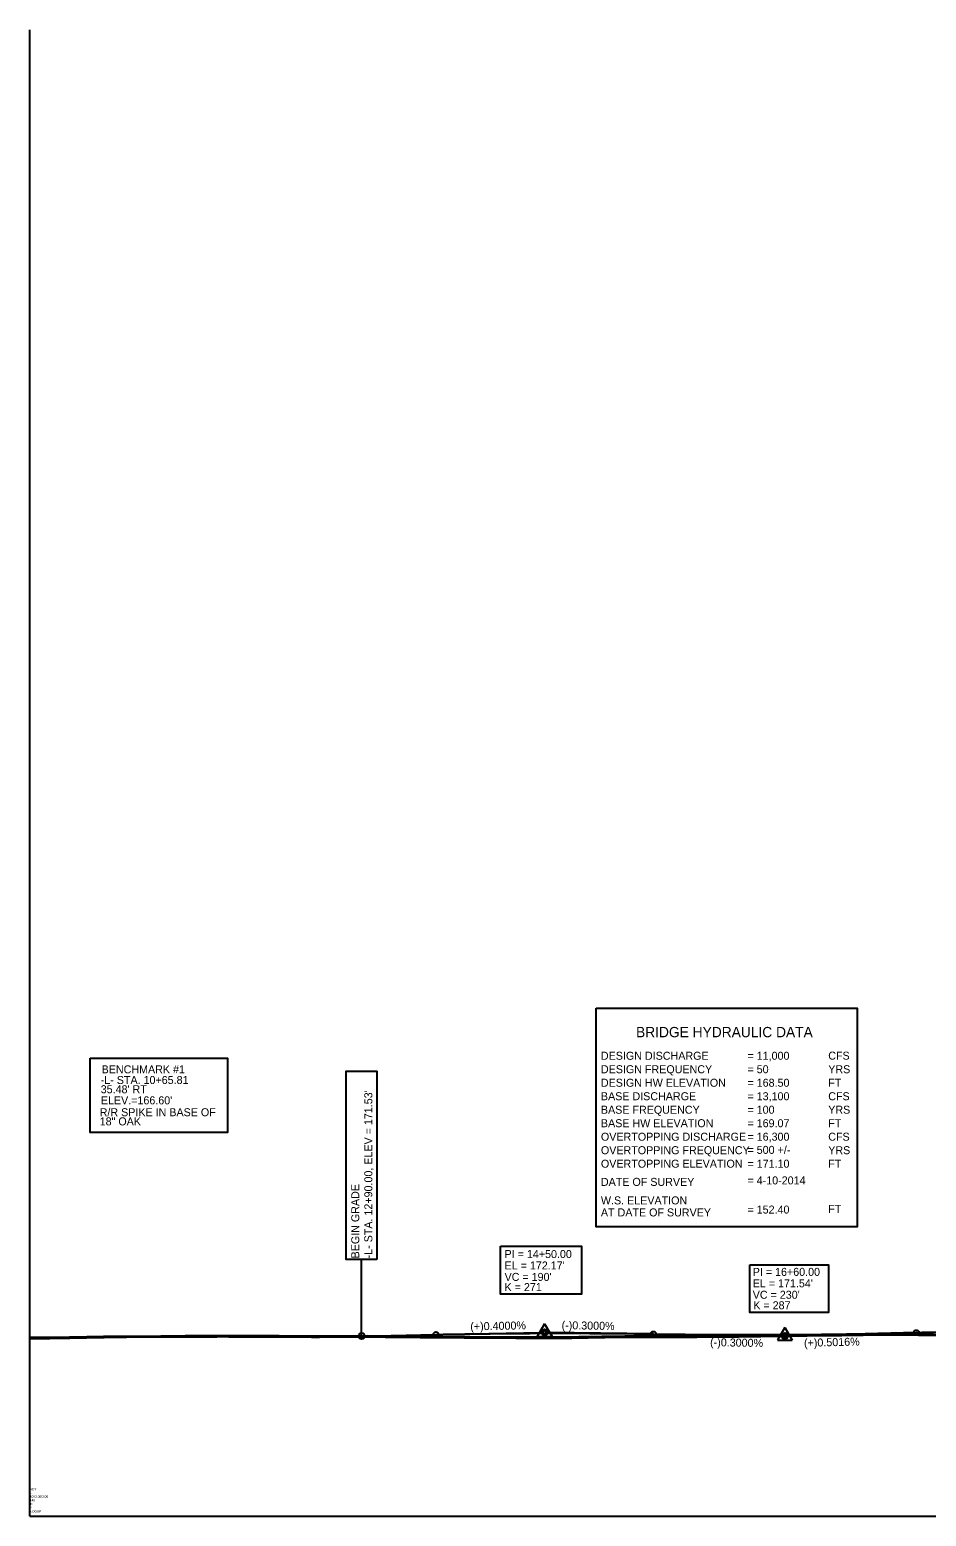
# Model space of a CAD drawing. Extents: x 2321227 to 2323611, y 920570 to 921870.
# Drawn here: x 2321227 to 2322011, y 920570 to 921870 of the extents above; entities that cross this region are included whole.
import ezdxf

# ---------------------------------------------------------------- set-up
doc = ezdxf.new("R2010")
doc.units = 0
for name, color, linetype in [('Exist Profile Cell', 7, 'Continuous'), ('Exist Vertical Profile Ground Line', 7, 'Continuous'), ('Prop Grid Mask', 7, 'Continuous'), ('Prop PFL Text', 7, 'Continuous'), ('Prop PFL VPI Symbol CELL', 7, 'Continuous'), ('Prop Vertical Profile Curve Label', 7, 'Continuous'), ('Prop Vertical Profile Grade', 7, 'Continuous'), ('Prop Vertical Profile Grade Label', 7, 'Continuous'), ('Prop VPI Label', 7, 'Continuous'), ('Scratch_Level_1', 7, 'Continuous'), ('Scratch_Level_2', 7, 'Continuous'), ('Scratch_Level_5', 7, 'Continuous')]:
    doc.layers.add(name, color=color, linetype=linetype)

# ---------------------------------------------------------------- blocks, each defined once
blk = doc.blocks.new('Profile VPI Symbol')
at = {"layer": 'Prop PFL VPI Symbol CELL'}
for p, q in [((-0.001, 0.147), (-0.13, -0.077)), ((-0.001, 0.147), (0.129, -0.077)), ((-0.13, -0.077), (0.129, -0.077))]:
    blk.add_line(p, q, dxfattribs=at)
for radius in [0.035, 0.024]:
    blk.add_circle((-0.001, -0.003), radius, dxfattribs=at)

msp = doc.modelspace()

# ---------------------------------------------------------------- linework, layer by layer
at = {"layer": 'Exist Profile Cell'}
for q in [(2321227, 921870.1), (2323610.7, 920570.1), (2321227, 920570.1)]:
    msp.add_line((2321227, 920570.1), q, dxfattribs=at)
at = {"layer": 'Exist Vertical Profile Ground Line'}
for p, q in [((2321227, 920725.5), (2321244.4, 920725.5)), ((2321244.4, 920725.5), (2321261.6, 920725.9)), ((2321261.6, 920725.9), (2321262, 920725.9)), ((2321262, 920725.9), (2321291.3, 920726.5)), ((2321291.3, 920726.5), (2321292, 920726.5)), ((2321292, 920726.5), (2321311.2, 920726.6)), ((2321311.2, 920726.6), (2321311.5, 920726.6)), ((2321311.5, 920726.6), (2321341.6, 920726.9)), ((2321341.6, 920726.9), (2321342.1, 920726.9)), ((2321342.1, 920726.9), (2321347.1, 920726.9)), ((2321347.1, 920726.9), (2321349, 920726.9)), ((2321349, 920726.9), (2321355.9, 920726.9)), ((2321355.9, 920726.9), (2321362.8, 920727)), ((2321362.8, 920727), (2321366.5, 920727)), ((2321366.5, 920727), (2321369.7, 920727)), ((2321369.7, 920727), (2321376.6, 920727.1)), ((2321376.6, 920727.1), (2321383.5, 920727.1)), ((2321383.5, 920727.1), (2321390.4, 920727.1)), ((2321390.4, 920727.1), (2321395.8, 920727.2)), ((2321395.8, 920727.2), (2321396.2, 920727.2)), ((2321396.2, 920727.2), (2321397.3, 920727.2)), ((2321397.3, 920727.2), (2321400.9, 920727.1)), ((2321400.9, 920727.1), (2321401.6, 920727.1)), ((2321401.6, 920727.1), (2321404.3, 920727.1)), ((2321404.3, 920727.1), (2321411.2, 920727.1)), ((2321411.2, 920727.1), (2321418.1, 920727.1)), ((2321418.1, 920727.1), (2321425, 920727)), ((2321425, 920727), (2321430.6, 920727)), ((2321430.6, 920727), (2321431.2, 920727)), ((2321431.2, 920727), (2321431.9, 920727)), ((2321431.9, 920727), (2321438.8, 920727)), ((2321438.8, 920727), (2321445, 920727)), ((2321445, 920727), (2321445.7, 920726.9)), ((2321445.7, 920726.9), (2321446.6, 920726.9)), ((2321446.6, 920726.9), (2321452.6, 920726.9)), ((2321452.6, 920726.9), (2321459.5, 920726.9)), ((2321459.5, 920726.9), (2321466.4, 920726.9)), ((2321466.4, 920726.9), (2321473.3, 920726.8)), ((2321473.3, 920726.8), (2321475.5, 920726.8)), ((2321475.5, 920726.8), (2321480.2, 920726.8)), ((2321480.2, 920726.8), (2321491.7, 920726.9)), ((2321491.7, 920726.9), (2321493.4, 920726.9)), ((2321493.4, 920726.9), (2321522.3, 920727)), ((2321522.3, 920727), (2321537.7, 920726.8)), ((2321537.7, 920726.8), (2321538.2, 920726.8)), ((2321538.2, 920726.8), (2321568.2, 920726.5)), ((2321568.2, 920726.5), (2321581.5, 920726.3)), ((2321581.5, 920726.3), (2321606.7, 920726.1)), ((2321606.7, 920726.1), (2321611.5, 920726.1)), ((2321611.5, 920726.1), (2321614.5, 920726)), ((2321614.5, 920726), (2321627.5, 920726)), ((2321627.5, 920726), (2321651.9, 920725.8)), ((2321651.9, 920725.8), (2321657.6, 920725.8)), ((2321657.6, 920725.8), (2321671.3, 920725.8)), ((2321671.3, 920725.8), (2321690.8, 920725.9)), ((2321690.8, 920725.9), (2321700.8, 920725.9)), ((2321700.8, 920725.9), (2321710.2, 920726.1)), ((2321710.2, 920726.1), (2321715.2, 920726.1)), ((2321715.2, 920726.1), (2321729.7, 920726.4)), ((2321729.7, 920726.4), (2321745.2, 920726.6)), ((2321745.2, 920726.6), (2321749.1, 920726.6)), ((2321749.1, 920726.6), (2321763.1, 920726.6)), ((2321763.1, 920726.6), (2321768.6, 920726.7)), ((2321768.6, 920726.7), (2321788.1, 920726.7)), ((2321788.1, 920726.7), (2321792.8, 920726.7)), ((2321792.8, 920726.7), (2321793.2, 920726.8)), ((2321793.2, 920726.8), (2321807.5, 920726.8)), ((2321807.5, 920726.8), (2321809.4, 920726.8)), ((2321809.4, 920726.8), (2321810.1, 920726.8)), ((2321810.1, 920726.8), (2321827, 920726.9)), ((2321827, 920726.9), (2321839.4, 920726.9)), ((2321839.4, 920726.9), (2321839.7, 920726.9)), ((2321839.7, 920726.9), (2321846.4, 920727)), ((2321846.4, 920727), (2321857.8, 920727.2)), ((2321857.8, 920727.2), (2321858.6, 920727.2)), ((2321858.6, 920727.2), (2321865.9, 920727.3)), ((2321865.9, 920727.3), (2321885.4, 920727.6)), ((2321885.4, 920727.6), (2321887.8, 920727.7)), ((2321887.8, 920727.7), (2321888.5, 920727.7)), ((2321888.5, 920727.7), (2321904.8, 920727.9)), ((2321904.8, 920727.9), (2321906.6, 920727.9)), ((2321906.6, 920727.9), (2321924.3, 920728.1)), ((2321924.3, 920728.1), (2321936.8, 920728.3)), ((2321936.8, 920728.3), (2321954, 920728.5)), ((2321954, 920728.5), (2321955.3, 920728.5)), ((2321955.3, 920728.5), (2321984.8, 920728.7)), ((2321984.8, 920728.7), (2321985.3, 920728.7)), ((2321985.3, 920728.7), (2322003.8, 920728.5)), ((2322003.8, 920728.5), (2322023, 920728.3))]:
    msp.add_line(p, q, dxfattribs=at)
at = {"layer": 'Prop Grid Mask'}
for points in [[(2321722, 921014.3), (2321950.3, 921014.3), (2321950.3, 920823.3), (2321722, 920823.3)], [(2321279.7, 920970.8), (2321399.7, 920970.8), (2321399.7, 920905.8), (2321279.7, 920905.8)], [(2321530.4, 920794.6), (2321503.6, 920794.6), (2321503.6, 920959.2), (2321530.4, 920959.2)], [(2321638.3, 920806.2), (2321709.2, 920806.2), (2321709.2, 920764.3), (2321638.3, 920764.3)], [(2321856.3, 920790.1), (2321925, 920790.1), (2321925, 920748.4), (2321856.3, 920748.4)]]:
    msp.add_lwpolyline(points, close=True, dxfattribs=at)
at = {"layer": 'Prop Vertical Profile Curve Label'}
msp.add_line((2321517, 920727.7), (2321517, 920794.6), dxfattribs=at)
for centre in [(2321582, 920729), (2321772, 920729.5), (2321772, 920729.5), (2322002, 920730.7)]:
    msp.add_circle(centre, 2.25, dxfattribs=at)
at = {"layer": 'Prop Vertical Profile Grade'}
for p, q in [((2322002, 920730.7), (2322372, 920739.9)), ((2321517, 920727.7), (2321582, 920729))]:
    msp.add_line(p, q, dxfattribs=at)
for points in [[(2321582, 920729), (2321585.8, 920729.1), (2321589.6, 920729.2), (2321593.4, 920729.2), (2321597.2, 920729.3), (2321601, 920729.4), (2321604.8, 920729.4), (2321608.6, 920729.5), (2321612.4, 920729.5), (2321616.2, 920729.6), (2321620, 920729.7), (2321623.8, 920729.7), (2321627.6, 920729.7), (2321631.4, 920729.8), (2321635.2, 920729.8), (2321639, 920729.9), (2321642.8, 920729.9), (2321646.6, 920729.9), (2321650.4, 920730), (2321654.2, 920730), (2321658, 920730), (2321661.8, 920730), (2321665.6, 920730.1), (2321669.4, 920730.1), (2321673.2, 920730.1), (2321677, 920730.1), (2321680.8, 920730.1), (2321684.6, 920730.1), (2321688.4, 920730.1), (2321692.2, 920730.1), (2321696, 920730.1), (2321699.8, 920730.1), (2321703.6, 920730.1), (2321707.4, 920730.1), (2321711.2, 920730.1), (2321715, 920730.1), (2321718.8, 920730), (2321722.6, 920730), (2321726.4, 920730), (2321730.2, 920730), (2321734, 920729.9), (2321737.8, 920729.9), (2321741.6, 920729.9), (2321745.4, 920729.8), (2321749.2, 920729.8), (2321753, 920729.8), (2321756.8, 920729.7), (2321760.6, 920729.7), (2321764.4, 920729.6), (2321768.2, 920729.6), (2321772, 920729.5)], [(2321772, 920729.5), (2321776.6, 920729.4), (2321781.2, 920729.4), (2321785.8, 920729.3), (2321790.4, 920729.3), (2321795, 920729.2), (2321799.6, 920729.2), (2321804.2, 920729.1), (2321808.8, 920729.1), (2321813.4, 920729), (2321818, 920729), (2321822.6, 920729), (2321827.2, 920728.9), (2321831.8, 920728.9), (2321836.4, 920728.9), (2321841, 920728.9), (2321845.6, 920728.9), (2321850.2, 920728.9), (2321854.8, 920728.9), (2321859.4, 920728.9), (2321864, 920728.9), (2321868.6, 920728.9), (2321873.2, 920728.9), (2321877.8, 920728.9), (2321882.4, 920728.9), (2321887, 920728.9), (2321891.6, 920729), (2321896.2, 920729), (2321900.8, 920729), (2321905.4, 920729), (2321910, 920729.1), (2321914.6, 920729.1), (2321919.2, 920729.2), (2321923.8, 920729.2), (2321928.4, 920729.3), (2321933, 920729.3), (2321937.6, 920729.4), (2321942.2, 920729.5), (2321946.8, 920729.5), (2321951.4, 920729.6), (2321956, 920729.7), (2321960.6, 920729.8), (2321965.2, 920729.9), (2321969.8, 920729.9), (2321974.4, 920730), (2321979, 920730.1), (2321983.6, 920730.2), (2321988.2, 920730.3), (2321992.8, 920730.4), (2321997.4, 920730.5), (2322002, 920730.7)]]:
    msp.add_spline(points, degree=3, dxfattribs=at)
at = {"layer": 'Prop VPI Label'}
for p, q in [((2321582, 920729), (2321674.2, 920730.9)), ((2321772, 920729.5), (2321679.7, 920730.9)), ((2321772, 920729.5), (2321884.2, 920727.8)), ((2322002, 920730.7), (2321889.7, 920727.8))]:
    msp.add_line(p, q, dxfattribs=at)
for centre in [(2321517, 920727.7), (2321677, 920730.9), (2321887, 920727.8)]:
    msp.add_circle(centre, 2.75, dxfattribs=at)
at = {"layer": 'Scratch_Level_1'}
for points in [[(2321227, 920726.6), (2321244.4, 920726.6), (2321261.6, 920727), (2321262, 920727), (2321291.3, 920727.6), (2321292, 920727.6), (2321311.2, 920727.7), (2321311.5, 920727.7), (2321341.6, 920728), (2321342.1, 920728), (2321347.1, 920728), (2321349, 920728), (2321355.9, 920728), (2321362.8, 920728.1), (2321366.5, 920728.1), (2321369.7, 920728.1), (2321376.6, 920728.2), (2321383.5, 920728.2), (2321390.4, 920728.2), (2321395.8, 920728.3), (2321396.2, 920728.3), (2321397.4, 920728.3), (2321400.9, 920728.2), (2321401.6, 920728.2), (2321430.6, 920728.1), (2321431.2, 920728.1), (2321445, 920728.1), (2321446.6, 920728), (2321475.5, 920727.9), (2321491.7, 920728), (2321493.4, 920728), (2321522.3, 920728.1), (2321537.7, 920727.9), (2321538.2, 920727.9), (2321568.2, 920727.6), (2321581.6, 920727.4), (2321606.8, 920727.2), (2321611.5, 920727.2), (2321614.5, 920727.1), (2321627.6, 920727.1), (2321651.9, 920726.9), (2321657.6, 920726.9), (2321671.3, 920726.9), (2321690.8, 920727), (2321700.8, 920727), (2321710.2, 920727.2), (2321715.2, 920727.2), (2321729.7, 920727.5), (2321745.2, 920727.7), (2321749.1, 920727.7), (2321763.1, 920727.7), (2321768.6, 920727.8), (2321788.1, 920727.8), (2321792.8, 920727.8), (2321793.2, 920727.9), (2321807.5, 920727.9), (2321809.4, 920727.9), (2321810.1, 920727.9), (2321839.4, 920728), (2321839.7, 920728), (2321857.8, 920728.3), (2321858.6, 920728.3), (2321887.8, 920728.8), (2321888.4, 920728.8), (2321906.6, 920729), (2321924.3, 920729.2), (2321936.8, 920729.4), (2321954, 920729.6), (2321984.8, 920729.8), (2321985.3, 920729.8), (2322023, 920729.4)], [(2321227, 920726.1), (2321244.4, 920726.2), (2321261.6, 920726.5), (2321262, 920726.5), (2321291.3, 920727.1), (2321292, 920727.1), (2321311.2, 920727.2), (2321311.5, 920727.2), (2321341.6, 920727.5), (2321342.1, 920727.5), (2321347.1, 920727.5), (2321349, 920727.5), (2321355.9, 920727.6), (2321362.8, 920727.6), (2321366.5, 920727.6), (2321369.7, 920727.6), (2321376.6, 920727.7), (2321383.5, 920727.7), (2321390.4, 920727.8), (2321395.8, 920727.8), (2321396.2, 920727.8), (2321397.3, 920727.8), (2321400.9, 920727.8), (2321401.6, 920727.8), (2321430.6, 920727.6), (2321431.2, 920727.6), (2321445, 920727.6), (2321446.6, 920727.6), (2321475.5, 920727.4), (2321491.7, 920727.5), (2321493.4, 920727.5), (2321522.3, 920727.6), (2321537.7, 920727.4), (2321538.2, 920727.4), (2321568.2, 920727.1), (2321581.6, 920727), (2321606.7, 920726.7), (2321611.5, 920726.7), (2321614.5, 920726.7), (2321627.6, 920726.6), (2321651.9, 920726.5), (2321657.6, 920726.4), (2321671.3, 920726.5), (2321690.8, 920726.5), (2321700.8, 920726.6), (2321710.2, 920726.7), (2321715.2, 920726.8), (2321729.7, 920727), (2321745.2, 920727.2), (2321749.1, 920727.2), (2321763.1, 920727.3), (2321768.6, 920727.3), (2321788.1, 920727.4), (2321792.8, 920727.4), (2321793.2, 920727.4), (2321807.5, 920727.4), (2321809.4, 920727.4), (2321810.1, 920727.4), (2321839.4, 920727.6), (2321839.7, 920727.6), (2321857.8, 920727.8), (2321858.6, 920727.9), (2321887.8, 920728.3), (2321888.4, 920728.3), (2321906.6, 920728.5), (2321924.3, 920728.7), (2321936.8, 920728.9), (2321954, 920729.1), (2321984.8, 920729.4), (2321985.3, 920729.4), (2322023, 920729)]]:
    msp.add_lwpolyline(points, dxfattribs=at)
at = {"layer": 'Scratch_Level_2'}
msp.add_lwpolyline([(2321527, 920727.6), (2321537, 920727.5), (2321547, 920727.3), (2321552, 920727.3), (2321557, 920727.2), (2321567, 920727.1), (2321577, 920727), (2321587, 920726.9), (2321597, 920726.8), (2321602, 920726.8), (2321607, 920726.8), (2321617, 920726.8), (2321627, 920726.8), (2321637, 920726.8), (2321647, 920726.9), (2321657, 920726.9), (2321667, 920726.9), (2321677, 920727), (2321687, 920727), (2321697, 920727), (2321707, 920727.2), (2321717, 920727.3), (2321727, 920727.5), (2321737, 920727.7), (2321747, 920727.8), (2321757, 920727.9), (2321767, 920727.9), (2321777, 920728), (2321787, 920728), (2321797, 920728.1), (2321807, 920728.2), (2321817, 920728.2), (2321827, 920728.3), (2321827, 920728.3), (2321837, 920728.4), (2321847, 920728.4), (2321852, 920728.4), (2321857, 920728.4), (2321867, 920728.4), (2321877, 920728.4), (2321887, 920728.4), (2321897, 920728.5), (2321907, 920728.7), (2321917, 920729), (2321924.3, 920729.1), (2321927, 920729.2), (2321937, 920729.4), (2321947, 920729.5), (2321957, 920729.7), (2321967, 920729.8), (2321977, 920730), (2321987, 920730.1), (2321997, 920729.9), (2322002, 920729.8), (2322007, 920731), (2322017, 920731.2)], dxfattribs=at)
at = {"layer": 'Scratch_Level_5'}
msp.add_line((2321874.3, 920727.5), (2322133.8, 920734), dxfattribs=at)

# ---------------------------------------------------------------- block references
at = {"layer": 'Prop Grid Mask', "xscale": 50, "yscale": 50}
for p in [(2321677, 920731.1), (2321887, 920727.9)]:
    msp.add_blockref('Profile VPI Symbol', p, dxfattribs=at)

# ---------------------------------------------------------------- texts
at = {"layer": 'Exist Profile Cell'}
for s, p in [('RDY', (2321227, 920592.8)), ('L', (2321227, 920589.6)), ('1000.000000', (2321227, 920586.3)), ('140', (2321227, 920583.1)), ('2', (2321227, 920576.6)), ('10', (2321227, 920579.8)), ('NOGAP', (2321227, 920573.3))]:
    msp.add_text(s, height=2, dxfattribs=at).set_placement(p)
at = {"layer": 'Prop PFL Text'}
for s, p in [('BENCHMARK #1', (2321289.8, 920957.4)), ("35.48' RT", (2321289, 920940)), ('-L- STA. 10+65.81', (2321289, 920948.1)), ("ELEV.=166.60'", (2321289.1, 920930.3)), ('R/R SPIKE IN BASE OF', (2321288.1, 920919.9)), ('18" OAK', (2321288.1, 920911.9))]:
    msp.add_text(s, height=7, rotation=360, dxfattribs=at).set_placement(p)
at = {"layer": 'Prop Vertical Profile Curve Label'}
for s, p in [("VC = 190'", (2321642, 920775.9)), ('K = 271', (2321642, 920767)), ("VC = 230'", (2321858.9, 920760.3)), ('K = 287', (2321859.4, 920751.1))]:
    msp.add_text(s, height=7, dxfattribs=at).set_placement(p)
at = {"layer": 'Prop Vertical Profile Grade Label'}
for s, rotation, p in [('(+)0.4000%', 1.1458, (2321612.1, 920732.6)), ('(-)0.3000%', 359.1406, (2321691.8, 920733.7)), ('(-)0.3000%', 359.1406, (2321821.6, 920718.8)), ('(+)0.5016%', 1.4367, (2321903.8, 920718.2))]:
    msp.add_text(s, height=7, rotation=rotation, dxfattribs=at).set_placement(p)
at = {"layer": 'Prop VPI Label'}
for s, height, p in [('BRIDGE HYDRAULIC DATA', 9, (2321756.9, 920989)), ('DESIGN DISCHARGE', 7, (2321726.2, 920969.3)), ('= 11,000  ', 7, (2321854.3, 920969.3)), ('CFS', 7, (2321924.9, 920969.4)), ('DESIGN FREQUENCY', 7, (2321726.2, 920957.5)), ('= 50 ', 7, (2321854.3, 920957.5)), ('YRS', 7, (2321924.9, 920957.5)), ('DESIGN HW ELEVATION', 7, (2321726.2, 920945.7)), ('= 168.50  ', 7, (2321854.3, 920945.7)), ('FT', 7, (2321924.9, 920945.7)), ('BASE DISCHARGE', 7, (2321726.2, 920933.9)), ('= 13,100  ', 7, (2321854.3, 920933.9)), ('CFS', 7, (2321924.9, 920933.9)), ('BASE FREQUENCY', 7, (2321726.2, 920922.1)), ('= 100', 7, (2321854.3, 920922.1)), ('YRS', 7, (2321924.9, 920922.1)), ('BASE HW ELEVATION', 7, (2321726.2, 920910.3)), ('= 169.07  ', 7, (2321854.3, 920910.3)), ('FT', 7, (2321924.9, 920910.3)), ('OVERTOPPING DISCHARGE', 7, (2321726.2, 920898.5)), ('= 16,300  ', 7, (2321854.3, 920898.5)), ('= 500 +/- ', 7, (2321854.3, 920887)), ('CFS', 7, (2321924.9, 920898.5)), ('OVERTOPPING FREQUENCY', 7, (2321726.2, 920886.7)), ('OVERTOPPING ELEVATION', 7, (2321726.2, 920874.9)), ('= 171.10  ', 7, (2321854.3, 920874.9)), ('YRS', 7, (2321924.9, 920886.7)), ('FT', 7, (2321924.9, 920874.9)), ('DATE OF SURVEY', 7, (2321726.2, 920859)), ('= 4-10-2014 ', 7, (2321854.3, 920860.3)), ('W.S. ELEVATION', 7, (2321726.2, 920842.8)), ('FT', 7, (2321924.9, 920835.4)), ('AT DATE OF SURVEY', 7, (2321726.2, 920832.3)), ('= 152.40  ', 7, (2321854.3, 920834.8)), ('PI = 14+50.00', 7, (2321642, 920795.9)), ("EL = 172.17'", 7, (2321642, 920785.9)), ('PI = 16+60.00', 7, (2321858.9, 920780.3)), ("EL = 171.54'", 7, (2321858.9, 920770.3))]:
    msp.add_text(s, height=height, dxfattribs=at).set_placement(p)
for s, p in [("-L- STA. 12+90.00, ELEV = 171.53'", (2321526.4, 920795.6)), ('BEGIN GRADE', (2321515, 920795.6))]:
    msp.add_text(s, height=7, rotation=90, dxfattribs=at).set_placement(p)

doc.saveas('drawing.dxf')
